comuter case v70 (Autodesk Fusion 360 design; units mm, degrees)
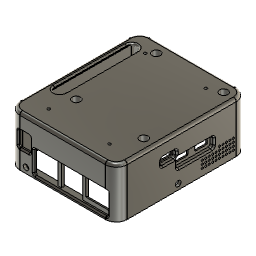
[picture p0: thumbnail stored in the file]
sketch "草图1" plane through (0, 0, 0) normal (0, 0, 1) x axis (1, 0, 0)
  line L1 (64.95, -85) -> (3.05, -85)
  line L2 (68, -3.05) -> (68, -81.95)
  line L3 (68, -3.05) -> (68, -81.95)
  line L4 (0, -81.95) -> (0, -3.05)
  line L5 (3.05, 0) -> (64.95, 0)
  line L6 (0, -81.95) -> (0, -3.05)
  line L7 (3.05, 0) -> (64.95, 0)
  line L8 (64.95, -85) -> (3.05, -85)
  line L9 (3.05, 3) -> (64.95, 3)
  line L10 (71, -3.05) -> (71, -81.95)
  line L11 (64.95, -88) -> (3.05, -88)
  line L12 (-3, -81.95) -> (-3, -3.05)
  line L13 (3.05, 5) -> (64.95, 5)
  line L14 (73, -3.05) -> (73, -81.95)
  line L15 (64.95, -90) -> (3.05, -90)
  line L16 (-5, -81.95) -> (-5, -3.05)
  arc A1 centre (65, -85) radius 0.05 clockwise from (64.95, -85) to (65.05, -84.9996)
  circle C1 centre (15.5, -61.5) radius 4.5
  circle C2 centre (64.5, -61.5) radius 1.475
  circle C3 centre (64.5, -3.5) radius 4.5
  arc A2 centre (68, -3) radius 0.05 clockwise from (68, -3.05) to (67.9996, -2.95)
  arc A3 centre (65, -3) radius 3 clockwise from (65.05, -0.0004) to (67.9996, -2.95)
  arc A4 centre (3, -82) radius 3 clockwise from (2.95, -84.9996) to (0.0004, -82.05)
  arc A5 centre (3, -85) radius 0.05 clockwise from (2.95, -84.9996) to (3.05, -85)
  arc A6 centre (65, -82) radius 3 clockwise from (67.9996, -82.05) to (65.05, -84.9996)
  arc A7 centre (0, -82) radius 0.05 clockwise from (0, -81.95) to (0.0004, -82.05)
  arc A8 centre (65, 0) radius 0.05 clockwise from (65.05, -0.0004) to (64.95, 0)
  arc A9 centre (68, -82) radius 0.05 clockwise from (67.9996, -82.05) to (68, -81.95)
  arc A10 centre (65, -85) radius 0.05 clockwise from (64.95, -85) to (65.05, -84.9996)
  arc A11 centre (3, -82) radius 3 clockwise from (2.95, -84.9996) to (0.0004, -82.05)
  arc A12 centre (3, -3) radius 3 clockwise from (0.0004, -2.95) to (2.95, -0.0004)
  arc A13 centre (68, -82) radius 0.05 clockwise from (67.9996, -82.05) to (68, -81.95)
  arc A14 centre (3, -3) radius 3 clockwise from (0.0004, -2.95) to (2.95, -0.0004)
  arc A15 centre (0, -3) radius 0.05 clockwise from (0.0004, -2.95) to (0, -3.05)
  arc A16 centre (0, -3) radius 0.05 clockwise from (0.0004, -2.95) to (0, -3.05)
  arc A17 centre (3, 0) radius 0.05 clockwise from (3.05, 0) to (2.95, -0.0004)
  arc A18 centre (65, -82) radius 3 clockwise from (67.9996, -82.05) to (65.05, -84.9996)
  arc A19 centre (3, 0) radius 0.05 clockwise from (3.05, 0) to (2.95, -0.0004)
  circle C4 centre (15.5, -3.5) radius 1.475
  arc A20 centre (65, -3) radius 3 clockwise from (65.05, -0.0004) to (67.9996, -2.95)
  circle C5 centre (64.5, -61.5) radius 4.5
  arc A21 centre (3, -85) radius 0.05 clockwise from (2.95, -84.9996) to (3.05, -85)
  circle C6 centre (15.5, -61.5) radius 1.475
  arc A22 centre (0, -82) radius 0.05 clockwise from (0, -81.95) to (0.0004, -82.05)
  circle C7 centre (15.5, -3.5) radius 4.5
  circle C8 centre (64.5, -3.5) radius 1.475
  arc A23 centre (68, -3) radius 0.05 clockwise from (68, -3.05) to (67.9996, -2.95)
  arc A24 centre (65, 0) radius 0.05 clockwise from (65.05, -0.0004) to (64.95, 0)
  arc A25 centre (3.05, 0) radius 3 clockwise from (2.9875, 2.9993) to (3.05, 3)
  arc A26 centre (64.95, 0) radius 3 clockwise from (64.95, 3) to (65.0125, 2.9993)
  arc A27 centre (65.05, -0.0004) radius 3 clockwise from (65.0125, 2.9993) to (65.1, 2.9992)
  arc A28 centre (65, -3) radius 6 clockwise from (65.1, 2.9992) to (70.9992, -2.9)
  arc A29 centre (67.9996, -2.95) radius 3 clockwise from (70.9992, -2.9) to (70.9993, -2.9875)
  arc A30 centre (68, -3.05) radius 3 clockwise from (70.9993, -2.9875) to (71, -3.05)
  arc A31 centre (68, -81.95) radius 3 clockwise from (71, -81.95) to (70.9993, -82.0125)
  arc A32 centre (67.9996, -82.05) radius 3 clockwise from (70.9993, -82.0125) to (70.9992, -82.1)
  arc A33 centre (65, -82) radius 6 clockwise from (70.9992, -82.1) to (65.1, -87.9992)
  arc A34 centre (65.05, -84.9996) radius 3 clockwise from (65.1, -87.9992) to (65.0125, -87.9993)
  arc A35 centre (64.95, -85) radius 3 clockwise from (65.0125, -87.9993) to (64.95, -88)
  arc A36 centre (3.05, -85) radius 3 clockwise from (3.05, -88) to (2.9875, -87.9993)
  arc A37 centre (2.95, -84.9996) radius 3 clockwise from (2.9875, -87.9993) to (2.9, -87.9992)
  arc A38 centre (3, -82) radius 6 clockwise from (2.9, -87.9992) to (-2.9992, -82.1)
  arc A39 centre (0.0004, -82.05) radius 3 clockwise from (-2.9992, -82.1) to (-2.9993, -82.0125)
  arc A40 centre (0, -81.95) radius 3 clockwise from (-2.9993, -82.0125) to (-3, -81.95)
  arc A41 centre (0, -3.05) radius 3 clockwise from (-3, -3.05) to (-2.9993, -2.9875)
  arc A42 centre (0.0004, -2.95) radius 3 clockwise from (-2.9993, -2.9875) to (-2.9992, -2.9)
  arc A43 centre (3, -3) radius 6 clockwise from (-2.9992, -2.9) to (2.9, 2.9992)
  arc A44 centre (2.95, -0.0004) radius 3 clockwise from (2.9, 2.9992) to (2.9875, 2.9993)
  arc A45 centre (3.05, 0) radius 5 clockwise from (2.9792, 4.9995) to (3.05, 5)
  arc A46 centre (64.95, 0) radius 5 clockwise from (64.95, 5) to (65.0208, 4.9995)
  arc A47 centre (65.05, -0.0004) radius 5 clockwise from (65.0208, 4.9995) to (65.1333, 4.9989)
  arc A48 centre (65, -3) radius 8 clockwise from (65.1333, 4.9989) to (72.9989, -2.8667)
  arc A49 centre (67.9996, -2.95) radius 5 clockwise from (72.9989, -2.8667) to (72.9995, -2.9792)
  arc A50 centre (68, -3.05) radius 5 clockwise from (72.9995, -2.9792) to (73, -3.05)
  arc A51 centre (68, -81.95) radius 5 clockwise from (73, -81.95) to (72.9995, -82.0208)
  arc A52 centre (67.9996, -82.05) radius 5 clockwise from (72.9995, -82.0208) to (72.9989, -82.1333)
  arc A53 centre (65, -82) radius 8 clockwise from (72.9989, -82.1333) to (65.1333, -89.9989)
  arc A54 centre (65.05, -84.9996) radius 5 clockwise from (65.1333, -89.9989) to (65.0208, -89.9995)
  arc A55 centre (64.95, -85) radius 5 clockwise from (65.0208, -89.9995) to (64.95, -90)
  arc A56 centre (3.05, -85) radius 5 clockwise from (3.05, -90) to (2.9792, -89.9995)
  arc A57 centre (2.95, -84.9996) radius 5 clockwise from (2.9792, -89.9995) to (2.8667, -89.9989)
  arc A58 centre (3, -82) radius 8 clockwise from (2.8667, -89.9989) to (-4.9989, -82.1333)
  arc A59 centre (0.0004, -82.05) radius 5 clockwise from (-4.9989, -82.1333) to (-4.9995, -82.0208)
  arc A60 centre (0, -81.95) radius 5 clockwise from (-4.9995, -82.0208) to (-5, -81.95)
  arc A61 centre (0, -3.05) radius 5 clockwise from (-5, -3.05) to (-4.9995, -2.9792)
  arc A62 centre (0.0004, -2.95) radius 5 clockwise from (-4.9995, -2.9792) to (-4.9989, -2.8667)
  arc A63 centre (3, -3) radius 8 clockwise from (-4.9989, -2.8667) to (2.8667, 4.9989)
  arc A64 centre (2.95, -0.0004) radius 5 clockwise from (2.8667, 4.9989) to (2.9792, 4.9995)
  circle C9 centre (64.5, -3.5) radius 2.975
  circle C10 centre (15.5, -3.5) radius 2.975
  circle C11 centre (15.5, -61.5) radius 2.975
  circle C12 centre (64.5, -61.5) radius 2.975
  equal C4 C8
  equal C4 C6
  equal C2 C6
  equal C3 C7
  equal C1 C7
  equal C1 C5
  perpendicular L2 L5
  perpendicular L5 L6
  dimension "d1" distance L5 L8 = 85
  dimension "d2" distance L3 L6 = 68
  dimension "d3" diameter C8 = 2.95
  dimension "d4" = 3
  dimension "d5" = 5 (= "3 mm + 2 mm")
  dimension "d6" diameter C3 = 9
  dimension "d7" = 1.5
  dimension "d8" = -1.5
  dimension "d9" = 1.5
  dimension "d10" = -1.5
  dimension "d33" = 2.25
  dimension "d57" = 1.5
extrude "拉伸1" new body sketch "草图1" profile of C1 C3 C5 C7 A25 A26 A27 A29 A30 A31 A32 A34 A35 A36 A37 A39 A40 A41 A42 A44 A38 L12 L9 A28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 against normal blind 2
extrude "拉伸2" add sketch "草图1" profile of A25 A26 A27 A29 A30 A31 A32 A34 A35 A36 A37 A39 A40 A41 A42 A44 A38 L12 L9 A28 A33 A43 L10 L11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 against normal blind 32 (magnitude of "-24 mm - 8 mm")
extrude "拉伸3" add sketch "草图1" profile of C1 C3 C5 C7 C9 C10 C11 C12 against normal blind 10
extrude "拉伸4" sketch "草图1" profile of C2 C4 C6 C8 C9 C10 C11 C12 blind 1.5
extrude "拉伸5" add of existing geometry blind 4.5
sketch "草图2" plane through (0, -90, 0) normal (0, -1, 0) x axis (1, 0, 0)
  line L1 (3.05, 0) -> (64.95, 0)
  line L2 (3.05, -36.5) -> (3.05, 0)
  line L3 (64.95, -36.5) -> (3.05, -36.5)
  line L4 (64.95, 0) -> (64.95, -36.5)
  line L5 (13, -34.5) -> (66.5, -34.5)
  line L6 (13, -18) -> (13, -34.5)
  line L7 (66.5, -18) -> (13, -18)
  line L8 (66.5, -34.5) -> (66.5, -18)
  line L9 (1.5011, -22.6) -> (10.4011, -22.6)
  line L10 (1.5011, -11.5) -> (1.5011, -22.6)
  line L11 (10.4011, -11.5) -> (1.5011, -11.5)
  line L12 (10.4011, -22.6) -> (10.4011, -11.5)
  line L13 (-4.9989, -36.5) -> (-4.9989, 0)
  point P6 (66.5, -34.5)
  point P7 (13, -34.5)
  point P8 (13, -18)
  point P10 (10.4011, -22.6)
  point P11 (1.5011, -22.6)
  point P12 (1.5011, -11.5)
  horizontal L5
  vertical L6
  horizontal L7
  vertical L8
  horizontal L9
  vertical L10
  horizontal L11
  vertical L12
  dimension "d22" distance P6 P7 = 53.5
  dimension "d23" distance P7 P8 = 16.5
  dimension "d24" distance L3 L5 = 2
  dimension "d28" = 16
  dimension "d151" distance P10 P11 = 8.9
  dimension "d152" distance P11 P12 = 11.1
  dimension "d153" distance L10 L13 = 6.5 (= "4.5 mm + 2 mm")
  dimension "d154" distance L1 L11 = 11.5
extrude "拉伸6" cut sketch "草图2" profile of L2 L4 L5 L6 L7 L8 L9 L10 L11 L12 to an object
extrude "拉伸7" cut of existing geometry blind -2
extrude "拉伸21" cut of existing geometry blind -2
sketch "草图3" plane through (0, 0, -36.5) normal (0, 0, -1) x axis (1, 0, 0)
  line L1 (-3, 81.95) -> (-3, 3.05)
  line L2 (64.95, 88) -> (3.05, 88)
  line L3 (71, 3.05) -> (71, 81.95)
  line L4 (3.05, -3) -> (64.95, -3)
  line L5 (64.95, -5) -> (3.05, -5)
  line L6 (73, 81.95) -> (73, 3.05)
  line L7 (3.05, 90) -> (64.95, 90)
  line L8 (-5, 3.05) -> (-5, 81.95)
  line L9 (-2.1962, 85) -> (70.1962, 85)
  arc A1 centre (2.95, 0.0004) radius 3 clockwise from (2.9875, -2.9993) to (2.9, -2.9992)
  arc A2 centre (3, 3) radius 6 clockwise from (2.9, -2.9992) to (-2.9992, 2.9)
  arc A3 centre (0.0004, 2.95) radius 3 clockwise from (-2.9992, 2.9) to (-2.9993, 2.9875)
  arc A4 centre (0, 3.05) radius 3 clockwise from (-2.9993, 2.9875) to (-3, 3.05)
  arc A5 centre (0, 81.95) radius 3 clockwise from (-3, 81.95) to (-2.9993, 82.0125)
  arc A6 centre (0.0004, 82.05) radius 3 clockwise from (-2.9993, 82.0125) to (-2.9992, 82.1)
  arc A7 centre (3, 82) radius 6 clockwise from (-2.9992, 82.1) to (2.9, 87.9992)
  arc A8 centre (2.95, 84.9996) radius 3 clockwise from (2.9, 87.9992) to (2.9875, 87.9993)
  arc A9 centre (3.05, 85) radius 3 clockwise from (2.9875, 87.9993) to (3.05, 88)
  arc A10 centre (64.95, 85) radius 3 clockwise from (64.95, 88) to (65.0125, 87.9993)
  arc A11 centre (65.05, 84.9996) radius 3 clockwise from (65.0125, 87.9993) to (65.1, 87.9992)
  arc A12 centre (65, 82) radius 6 clockwise from (65.1, 87.9992) to (70.9992, 82.1)
  arc A13 centre (67.9996, 82.05) radius 3 clockwise from (70.9992, 82.1) to (70.9993, 82.0125)
  arc A14 centre (68, 81.95) radius 3 clockwise from (70.9993, 82.0125) to (71, 81.95)
  arc A15 centre (68, 3.05) radius 3 clockwise from (71, 3.05) to (70.9993, 2.9875)
  arc A16 centre (67.9996, 2.95) radius 3 clockwise from (70.9993, 2.9875) to (70.9992, 2.9)
  arc A17 centre (65, 3) radius 6 clockwise from (70.9992, 2.9) to (65.1, -2.9992)
  arc A18 centre (65.05, 0.0004) radius 3 clockwise from (65.1, -2.9992) to (65.0125, -2.9993)
  arc A19 centre (64.95, 0) radius 3 clockwise from (65.0125, -2.9993) to (64.95, -3)
  arc A20 centre (3.05, 0) radius 3 clockwise from (3.05, -3) to (2.9875, -2.9993)
  arc A21 centre (2.95, 0.0004) radius 5 clockwise from (2.9792, -4.9995) to (2.8667, -4.9989)
  arc A22 centre (3.05, 0) radius 5 clockwise from (3.05, -5) to (2.9792, -4.9995)
  arc A23 centre (64.95, 0) radius 5 clockwise from (65.0208, -4.9995) to (64.95, -5)
  arc A24 centre (65.05, 0.0004) radius 5 clockwise from (65.1333, -4.9989) to (65.0208, -4.9995)
  arc A25 centre (65, 3) radius 8 clockwise from (72.9989, 2.8667) to (65.1333, -4.9989)
  arc A26 centre (67.9996, 2.95) radius 5 clockwise from (72.9995, 2.9792) to (72.9989, 2.8667)
  arc A27 centre (68, 3.05) radius 5 clockwise from (73, 3.05) to (72.9995, 2.9792)
  arc A28 centre (68, 81.95) radius 5 clockwise from (72.9995, 82.0208) to (73, 81.95)
  arc A29 centre (67.9996, 82.05) radius 5 clockwise from (72.9989, 82.1333) to (72.9995, 82.0208)
  arc A30 centre (65, 82) radius 8 clockwise from (65.1333, 89.9989) to (72.9989, 82.1333)
  arc A31 centre (65.05, 84.9996) radius 5 clockwise from (65.0208, 89.9995) to (65.1333, 89.9989)
  arc A32 centre (64.95, 85) radius 5 clockwise from (64.95, 90) to (65.0208, 89.9995)
  arc A33 centre (3.05, 85) radius 5 clockwise from (2.9792, 89.9995) to (3.05, 90)
  arc A34 centre (2.95, 84.9996) radius 5 clockwise from (2.8667, 89.9989) to (2.9792, 89.9995)
  arc A35 centre (3, 82) radius 8 clockwise from (-4.9989, 82.1333) to (2.8667, 89.9989)
  arc A36 centre (0.0004, 82.05) radius 5 clockwise from (-4.9995, 82.0208) to (-4.9989, 82.1333)
  arc A37 centre (0, 81.95) radius 5 clockwise from (-5, 81.95) to (-4.9995, 82.0208)
  arc A38 centre (0, 3.05) radius 5 clockwise from (-4.9995, 2.9792) to (-5, 3.05)
  arc A39 centre (0.0004, 2.95) radius 5 clockwise from (-4.9989, 2.8667) to (-4.9995, 2.9792)
  arc A40 centre (3, 3) radius 8 clockwise from (2.8667, -4.9989) to (-4.9989, 2.8667)
  point P70 (70.1962, 85)
  point P71 (-2.1962, 85)
  coincident A12 P70
  coincident A7 P71
  parallel L7 L9
  dimension "d105" distance L2 L9 = 3
sketch "草图4" plane through (73, 0, 0) normal (1, 0, 0) x axis (0, 1, 0)
  line L1 (-81.95, 0) -> (-3.05, 0)
  line L2 (-81.95, -36.5) -> (-81.95, 0)
  line L3 (-3.05, -36.5) -> (-81.95, -36.5)
  line L4 (-3.05, 0) -> (-3.05, -36.5)
  line L5 (-42.5, 0) -> (-42.5, -36.5)
  line L6 (-81.95, -17.7) -> (-3.05, -17.7)
  line L7 (-44, -17.7) -> (-21, -17.7)
  line L8 (-44, -21.2) -> (-44, -17.7)
  line L9 (-21, -21.2) -> (-44, -21.2)
  line L10 (-21, -17.7) -> (-21, -21.2)
  line L11 (-32.5, -17.7) -> (-32.5, -21.2)
  line L12 (-30, -17.7) -> (-35, -17.7)
  line L13 (-30, -21.2) -> (-30, -17.7)
  line L14 (-35, -21.2) -> (-30, -21.2)
  line L15 (-35, -17.7) -> (-35, -21.2)
  line L16 (-30, -21.2) -> (-35, -17.7)
  line L17 (-35, -21.2) -> (-30, -17.7)
  line L18 (-81.95, -11.5) -> (-42.5, -11.5)
  line L19 (-56.57, -11.5) -> (-47.07, -11.5)
  line L20 (-56.57, -15) -> (-56.57, -11.5)
  line L21 (-47.07, -15) -> (-56.57, -15)
  line L22 (-47.07, -11.5) -> (-47.07, -15)
  line L23 (-57.57, -10.5) -> (-46.07, -10.5)
  line L24 (-57.57, -16) -> (-57.57, -10.5)
  line L25 (-46.07, -16) -> (-57.57, -16)
  line L26 (-46.07, -10.5) -> (-46.07, -16)
  line L27 (-46, -15.7) -> (-19, -15.7)
  line L28 (-46, -23.2) -> (-46, -15.7)
  line L29 (-19, -23.2) -> (-46, -23.2)
  line L30 (-19, -15.7) -> (-19, -23.2)
  circle C1 centre (-77.5, -30) radius 1.125
  circle C2 centre (-77.5, -30) radius 2.125
  circle C3 centre (-77.5, -30) radius 4.125
  circle C4 centre (-7.5, -30) radius 4.125
  circle C5 centre (-7.5, -30) radius 2.125
  circle C6 centre (-7.5, -30) radius 1.125
  circle C7 centre (-42.5, -26.5) radius 0.75
  circle C8 centre (-42.5, -31.5) radius 0.75
  circle C9 centre (-40, -31.5) radius 0.75
  circle C10 centre (-37.5, -31.5) radius 0.75
  circle C11 centre (-35, -31.5) radius 0.75
  circle C12 centre (-32.5, -31.5) radius 0.75
  circle C13 centre (-42.5, -29) radius 0.75
  circle C14 centre (-40, -29) radius 0.75
  circle C15 centre (-37.5, -29) radius 0.75
  circle C16 centre (-35, -29) radius 0.75
  circle C17 centre (-32.5, -29) radius 0.75
  circle C18 centre (-40, -26.5) radius 0.75
  circle C19 centre (-37.5, -26.5) radius 0.75
  circle C20 centre (-35, -26.5) radius 0.75
  circle C21 centre (-32.5, -26.5) radius 0.75
  circle C22 centre (-42.5, -24) radius 0.75
  circle C23 centre (-40, -24) radius 0.75
  circle C24 centre (-37.5, -24) radius 0.75
  circle C25 centre (-35, -24) radius 0.75
  circle C26 centre (-32.5, -24) radius 0.75
  circle C27 centre (-42.5, -21.5) radius 0.75
  circle C28 centre (-40, -21.5) radius 0.75
  circle C29 centre (-37.5, -21.5) radius 0.75
  circle C30 centre (-35, -21.5) radius 0.75
  circle C31 centre (-32.5, -21.5) radius 0.75
  circle C32 centre (-30, -31.5) radius 0.75
  circle C33 centre (-27.5, -31.5) radius 0.75
  circle C34 centre (-25, -31.5) radius 0.75
  circle C35 centre (-22.5, -31.5) radius 0.75
  circle C36 centre (-20, -31.5) radius 0.75
  circle C37 centre (-17.5, -31.5) radius 0.75
  circle C38 centre (-15, -31.5) radius 0.75
  circle C39 centre (-12.5, -31.5) radius 0.75
  circle C40 centre (-10, -31.5) radius 0.75
  circle C41 centre (-7.5, -31.5) radius 0.75
  circle C42 centre (-5, -31.5) radius 0.75
  circle C43 centre (-30, -29) radius 0.75
  circle C44 centre (-27.5, -29) radius 0.75
  circle C45 centre (-25, -29) radius 0.75
  circle C46 centre (-22.5, -29) radius 0.75
  circle C47 centre (-20, -29) radius 0.75
  circle C48 centre (-17.5, -29) radius 0.75
  circle C49 centre (-15, -29) radius 0.75
  circle C50 centre (-12.5, -29) radius 0.75
  circle C51 centre (-10, -29) radius 0.75
  circle C52 centre (-7.5, -29) radius 0.75
  circle C53 centre (-5, -29) radius 0.75
  circle C54 centre (-30, -26.5) radius 0.75
  circle C55 centre (-27.5, -26.5) radius 0.75
  circle C56 centre (-25, -26.5) radius 0.75
  circle C57 centre (-22.5, -26.5) radius 0.75
  circle C58 centre (-20, -26.5) radius 0.75
  circle C59 centre (-17.5, -26.5) radius 0.75
  circle C60 centre (-15, -26.5) radius 0.75
  circle C61 centre (-12.5, -26.5) radius 0.75
  circle C62 centre (-10, -26.5) radius 0.75
  circle C63 centre (-7.5, -26.5) radius 0.75
  circle C64 centre (-5, -26.5) radius 0.75
  circle C65 centre (-30, -24) radius 0.75
  circle C66 centre (-27.5, -24) radius 0.75
  circle C67 centre (-25, -24) radius 0.75
  circle C68 centre (-22.5, -24) radius 0.75
  circle C69 centre (-20, -24) radius 0.75
  circle C70 centre (-17.5, -24) radius 0.75
  circle C71 centre (-15, -24) radius 0.75
  circle C72 centre (-12.5, -24) radius 0.75
  circle C73 centre (-10, -24) radius 0.75
  circle C74 centre (-7.5, -24) radius 0.75
  circle C75 centre (-5, -24) radius 0.75
  circle C76 centre (-30, -21.5) radius 0.75
  circle C77 centre (-27.5, -21.5) radius 0.75
  circle C78 centre (-25, -21.5) radius 0.75
  circle C79 centre (-22.5, -21.5) radius 0.75
  circle C80 centre (-20, -21.5) radius 0.75
  circle C81 centre (-17.5, -21.5) radius 0.75
  circle C82 centre (-15, -21.5) radius 0.75
  circle C83 centre (-12.5, -21.5) radius 0.75
  circle C84 centre (-10, -21.5) radius 0.75
  circle C85 centre (-7.5, -21.5) radius 0.75
  circle C86 centre (-5, -21.5) radius 0.75
  point P6 (-42.5, -36.5)
  point P7 (-42.5, 0)
  point P14 (-42.5, -26.5)
  point P94 (-3.05, -17.7)
  point P95 (-81.95, -17.7)
  point P96 (-21, -17.7)
  point P100 (-32.5, -21.2)
  point P101 (-32.5, -17.7)
  point P106 (-32.5, -19.45)
  point P102 (-35, -17.7)
  point P107 (-42.5, -11.5)
  point P108 (-81.95, -11.5)
  point P109 (-47.07, -11.5)
  point P8 (-77.5, -30)
  point P97 (-44, -17.7)
  point P98 (-44, -21.2)
  point P110 (-56.57, -11.5)
  point P111 (-56.57, -15)
  point P112 (-47.07, -15)
  midpoint L3 P6
  midpoint L1 P7
  concentric C1 C2
  concentric C2 C3
  symmetric L5 C1 C6
  symmetric L5 C2 C5
  symmetric L5 C3 C4
  coincident L5 P14
  coincident L4 P94
  coincident L2 P95
  perpendicular L2 L6
  horizontal L7
  vertical L8
  horizontal L9
  vertical L10
  coincident L6 P96
  midpoint L9 P100
  midpoint L7 P101
  horizontal L12
  perpendicular L12 L13
  parallel L12 L14
  parallel L13 L15
  coincident L16 P106
  coincident L17 P106
  coincident L7 P102
  midpoint L11 P106
  coincident L5 P107
  coincident L2 P108
  perpendicular L2 L18
  horizontal L19
  vertical L20
  horizontal L21
  vertical L22
  coincident L18 P109
  dimension "d31" distance L5 P8 = 35
  dimension "d32" distance C1 C2 = 1
  dimension "d33" diameter C1 = 2.25
  dimension "d34" distance C2 C3 = 2
  dimension "d57" diameter C7 = 1.5
  dimension "d58" distance L3 P14 = 10
  dimension "d66" distance L1 L6 = 17.7
  dimension "d67" distance P97 P98 = 3.5
  dimension "d69" distance L8 L10 = 23
  dimension "d73" distance L5 L8 = 1.5
  dimension "d74" distance L13 L15 = 5
  dimension "d75" distance L1 L18 = 11.5
  dimension "d76" distance P110 P111 = 3.5
  dimension "d77" distance P111 P112 = 9.5
  dimension "d78" distance L8 L22 = 3.07 (= "4.88 mm - 1.55 mm - ( ( 9.5 - 8.98 ) / 2 ) * 1 mm")
  dimension "d79" = 1
  dimension "d89" = 2 (= "( ( 7.5 - 3.5 ) / 2 ) * 1 mm")
  dimension "d61" R-Pattern1-uDistance = 2.5
  dimension "d62" R-Pattern1-vDistance = 2.5
sketch "草图5" plane through (0, 5, 0) normal (0, 1, 0) x axis (-1, 0, 0)
  line L1 (-64.95, 0) -> (-3.05, 0)
  line L2 (-64.95, -36.5) -> (-64.95, 0)
  line L3 (-3.05, -36.5) -> (-64.95, -36.5)
  line L4 (-3.05, 0) -> (-3.05, -36.5)
  line L5 (-64.95, -36.5) -> (-3.05, -36.5)
  line L6 (-64.95, -16.5) -> (-64.95, -36.5)
  line L7 (-3.05, -16.5) -> (-64.95, -16.5)
  line L8 (-3.05, -36.5) -> (-3.05, -16.5)
  line L9 (-34, -16.5) -> (-34, -36.5)
  line L10 (-10, -11.5) -> (-3.05, -11.5)
  line L11 (-64.95, -11.5) -> (-10, -11.5)
  line L12 (-63.2989, -11.5) -> (-15.2989, -11.5)
  line L13 (-63.2989, -12.5) -> (-63.2989, -11.5)
  line L14 (-15.2989, -12.5) -> (-63.2989, -12.5)
  line L15 (-15.2989, -11.5) -> (-15.2989, -12.5)
  line L16 (-72.9989, -36.5) -> (-72.9989, 0)
  circle C1 centre (-34, -26.5) radius 0.75
  circle C2 centre (-61.5, -31.5) radius 0.75
  circle C3 centre (-59, -31.5) radius 0.75
  circle C4 centre (-56.5, -31.5) radius 0.75
  circle C5 centre (-54, -31.5) radius 0.75
  circle C6 centre (-51.5, -31.5) radius 0.75
  circle C7 centre (-49, -31.5) radius 0.75
  circle C8 centre (-46.5, -31.5) radius 0.75
  circle C9 centre (-44, -31.5) radius 0.75
  circle C10 centre (-41.5, -31.5) radius 0.75
  circle C11 centre (-39, -31.5) radius 0.75
  circle C12 centre (-36.5, -31.5) radius 0.75
  circle C13 centre (-34, -31.5) radius 0.75
  circle C14 centre (-31.5, -31.5) radius 0.75
  circle C15 centre (-29, -31.5) radius 0.75
  circle C16 centre (-26.5, -31.5) radius 0.75
  circle C17 centre (-24, -31.5) radius 0.75
  circle C18 centre (-21.5, -31.5) radius 0.75
  circle C19 centre (-19, -31.5) radius 0.75
  circle C20 centre (-16.5, -31.5) radius 0.75
  circle C21 centre (-14, -31.5) radius 0.75
  circle C22 centre (-11.5, -31.5) radius 0.75
  circle C23 centre (-9, -31.5) radius 0.75
  circle C24 centre (-6.5, -31.5) radius 0.75
  circle C25 centre (-61.5, -29) radius 0.75
  circle C26 centre (-59, -29) radius 0.75
  circle C27 centre (-56.5, -29) radius 0.75
  circle C28 centre (-54, -29) radius 0.75
  circle C29 centre (-51.5, -29) radius 0.75
  circle C30 centre (-49, -29) radius 0.75
  circle C31 centre (-46.5, -29) radius 0.75
  circle C32 centre (-44, -29) radius 0.75
  circle C33 centre (-41.5, -29) radius 0.75
  circle C34 centre (-39, -29) radius 0.75
  circle C35 centre (-36.5, -29) radius 0.75
  circle C36 centre (-34, -29) radius 0.75
  circle C37 centre (-31.5, -29) radius 0.75
  circle C38 centre (-29, -29) radius 0.75
  circle C39 centre (-26.5, -29) radius 0.75
  circle C40 centre (-24, -29) radius 0.75
  circle C41 centre (-21.5, -29) radius 0.75
  circle C42 centre (-19, -29) radius 0.75
  circle C43 centre (-16.5, -29) radius 0.75
  circle C44 centre (-14, -29) radius 0.75
  circle C45 centre (-11.5, -29) radius 0.75
  circle C46 centre (-9, -29) radius 0.75
  circle C47 centre (-6.5, -29) radius 0.75
  circle C48 centre (-61.5, -26.5) radius 0.75
  circle C49 centre (-59, -26.5) radius 0.75
  circle C50 centre (-56.5, -26.5) radius 0.75
  circle C51 centre (-54, -26.5) radius 0.75
  circle C52 centre (-51.5, -26.5) radius 0.75
  circle C53 centre (-49, -26.5) radius 0.75
  circle C54 centre (-46.5, -26.5) radius 0.75
  circle C55 centre (-44, -26.5) radius 0.75
  circle C56 centre (-41.5, -26.5) radius 0.75
  circle C57 centre (-39, -26.5) radius 0.75
  circle C58 centre (-36.5, -26.5) radius 0.75
  circle C59 centre (-31.5, -26.5) radius 0.75
  circle C60 centre (-29, -26.5) radius 0.75
  circle C61 centre (-26.5, -26.5) radius 0.75
  circle C62 centre (-24, -26.5) radius 0.75
  circle C63 centre (-21.5, -26.5) radius 0.75
  circle C64 centre (-19, -26.5) radius 0.75
  circle C65 centre (-16.5, -26.5) radius 0.75
  circle C66 centre (-14, -26.5) radius 0.75
  circle C67 centre (-11.5, -26.5) radius 0.75
  circle C68 centre (-9, -26.5) radius 0.75
  circle C69 centre (-6.5, -26.5) radius 0.75
  circle C70 centre (-61.5, -24) radius 0.75
  circle C71 centre (-59, -24) radius 0.75
  circle C72 centre (-56.5, -24) radius 0.75
  circle C73 centre (-54, -24) radius 0.75
  circle C74 centre (-51.5, -24) radius 0.75
  circle C75 centre (-49, -24) radius 0.75
  circle C76 centre (-46.5, -24) radius 0.75
  circle C77 centre (-44, -24) radius 0.75
  circle C78 centre (-41.5, -24) radius 0.75
  circle C79 centre (-39, -24) radius 0.75
  circle C80 centre (-36.5, -24) radius 0.75
  circle C81 centre (-34, -24) radius 0.75
  circle C82 centre (-31.5, -24) radius 0.75
  circle C83 centre (-29, -24) radius 0.75
  circle C84 centre (-26.5, -24) radius 0.75
  circle C85 centre (-24, -24) radius 0.75
  circle C86 centre (-21.5, -24) radius 0.75
  circle C87 centre (-19, -24) radius 0.75
  circle C88 centre (-16.5, -24) radius 0.75
  circle C89 centre (-14, -24) radius 0.75
  circle C90 centre (-11.5, -24) radius 0.75
  circle C91 centre (-9, -24) radius 0.75
  circle C92 centre (-6.5, -24) radius 0.75
  circle C93 centre (-61.5, -21.5) radius 0.75
  circle C94 centre (-59, -21.5) radius 0.75
  circle C95 centre (-56.5, -21.5) radius 0.75
  circle C96 centre (-54, -21.5) radius 0.75
  circle C97 centre (-51.5, -21.5) radius 0.75
  circle C98 centre (-49, -21.5) radius 0.75
  circle C99 centre (-46.5, -21.5) radius 0.75
  circle C100 centre (-44, -21.5) radius 0.75
  circle C101 centre (-41.5, -21.5) radius 0.75
  circle C102 centre (-39, -21.5) radius 0.75
  circle C103 centre (-36.5, -21.5) radius 0.75
  circle C104 centre (-34, -21.5) radius 0.75
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  point P8 (-64.95, -16.5)
  point P5 (-3.05, -36.5)
  point P6 (-3.05, -36.5)
  point P10 (-34, -36.5)
  point P11 (-34, -16.5)
  point P12 (-34, -26.5)
  point P128 (-3.05, -11.5)
  point P130 (-64.95, -11.5)
  point P131 (-15.2989, -11.5)
  point P127 (-6.4, -15.5)
  point P133 (-63.2989, -12.5)
  point P134 (-15.2989, -12.5)
  point P132 (-63.2989, -11.5)
  point P135 (-54.8989, -18.25)
  horizontal L5
  vertical L6
  horizontal L7
  vertical L8
  coincident L2 P8
  coincident P5 P6
  midpoint L5 P10
  midpoint L7 P11
  midpoint L9 P12
  coincident L4 P128
  perpendicular L4 L10
  coincident L2 P130
  perpendicular L2 L11
  horizontal L12
  vertical L13
  horizontal L14
  vertical L15
  coincident L11 P131
  dimension "d49" distance L5 L7 = 20
  dimension "d50" diameter C1 = 1.5
  dimension "d97" diameter = 6
  dimension "d100" distance L4 P127 = 3.35
  dimension "d101" distance L1 P127 = 15.5
  dimension "d136" distance L1 L11 = 11.5
  dimension "d137" distance P133 P134 = 48 (= "33 mm + 15 mm")
  dimension "d138" distance P132 P133 = 1
  dimension "d143" diameter = 1.5
  dimension "d145" distance P135 L16 = 18.1 (= "14.7 mm + 3.2 mm + 0.2 mm")
  dimension "d148" distance L7 P135 = 1.75
  dimension "d197" distance L13 P135 = 8.4 (= "10 mm - 1.6 mm")
  dimension "d53" R-Pattern1-uDistance = 2.5
  dimension "d54" R-Pattern1-vDistance = 2.5
extrude "拉伸13" cut sketch "草图5" profile of C1 C2 C3 C4 C5 C6 C7 C8 C9 C10 C11 C12 C13 C14 C15 C16 C17 C18 C19 C25 C26 C27 C28 C29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 to an object
extrude "拉伸14" cut sketch "草图4" profile of C33 C34 C35 C36 C37 C38 C39 C40 C41 C42 C44 C45 C46 C47 C48 C49 C50 C51 C52 C53 C55 C56 C57 C58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 to an object
extrude "拉伸15" cut sketch "草图4" profile of L7 L8 L9 L10 L12 L13 L14 L15 L19 L20 L21 L22 L24 L26 L25 L23 L30 L28 L27 L29 to an object
fillet "圆角5" radius 1.5
sketch "草图6" plane through (71, 0, 0) normal (-1, 0, 0) x axis (0, -1, 0)
  line L1 (20.5, -23.2) -> (44.5, -23.2)
  line L2 (19, -17.2) -> (19, -21.7)
  line L3 (44.5, -15.7) -> (20.5, -15.7)
  line L4 (46, -21.7) -> (46, -17.2)
  line L5 (47.57, -16) -> (56.07, -16)
  line L6 (46.07, -12) -> (46.07, -14.5)
  line L7 (56.07, -10.5) -> (47.57, -10.5)
  line L8 (57.57, -14.5) -> (57.57, -12)
  line L9 (3.05, -2) -> (81.95, -2)
  line L10 (3.05, -36.5) -> (3.05, -2)
  line L11 (81.95, -36.5) -> (3.05, -36.5)
  line L12 (81.95, -2) -> (81.95, -36.5)
  line L13 (47, -21.7) -> (47, -17.2)
  line L14 (20.5, -24.2) -> (44.5, -24.2)
  line L15 (18, -17.2) -> (18, -21.7)
  line L16 (44.5, -14.7) -> (20.5, -14.7)
  line L17 (47.57, -17) -> (56.07, -17)
  line L18 (58.57, -14.5) -> (58.57, -12)
  line L19 (56.07, -9.5) -> (47.57, -9.5)
  line L20 (45.07, -12) -> (45.07, -14.5)
  arc A1 centre (20.5, -21.7) radius 1.5 clockwise from (20.5, -23.2) to (19, -21.7)
  arc A2 centre (20.5, -17.2) radius 1.5 clockwise from (19, -17.2) to (20.5, -15.7)
  arc A3 centre (44.5, -17.2) radius 1.5 clockwise from (44.5, -15.7) to (46, -17.2)
  arc A4 centre (44.5, -21.7) radius 1.5 clockwise from (46, -21.7) to (44.5, -23.2)
  arc A5 centre (47.57, -14.5) radius 1.5 clockwise from (47.57, -16) to (46.07, -14.5)
  arc A6 centre (47.57, -12) radius 1.5 clockwise from (46.07, -12) to (47.57, -10.5)
  arc A7 centre (56.07, -12) radius 1.5 clockwise from (56.07, -10.5) to (57.57, -12)
  arc A8 centre (56.07, -14.5) radius 1.5 clockwise from (57.57, -14.5) to (56.07, -16)
  circle C1 centre (20, -26.5) radius 0.75
  circle C2 centre (20, -29) radius 0.75
  circle C3 centre (20, -31.5) radius 0.75
  circle C4 centre (12.5, -26.5) radius 0.75
  circle C5 centre (15, -24) radius 0.75
  circle C6 centre (17.5, -29) radius 0.75
  circle C7 centre (15, -29) radius 0.75
  circle C8 centre (12.5, -29) radius 0.75
  circle C9 centre (15, -31.5) radius 0.75
  circle C10 centre (22.5, -31.5) radius 0.75
  circle C11 centre (25, -31.5) radius 0.75
  circle C12 centre (27.5, -29) radius 0.75
  circle C13 centre (22.5, -29) radius 0.75
  circle C14 centre (25, -29) radius 0.75
  circle C15 centre (5, -24) radius 0.75
  circle C16 centre (10, -24) radius 0.75
  circle C17 centre (25, -26.5) radius 0.75
  circle C18 centre (12.5, -24) radius 0.75
  circle C19 centre (15, -26.5) radius 0.75
  circle C20 centre (17.5, -26.5) radius 0.75
  circle C21 centre (12.5, -31.5) radius 0.75
  circle C22 centre (17.5, -31.5) radius 0.75
  circle C23 centre (27.5, -31.5) radius 0.75
  circle C24 centre (27.5, -26.5) radius 0.75
  circle C25 centre (22.5, -26.5) radius 0.75
  circle C26 centre (7.5, -24) radius 0.75
  arc A9 centre (44.5, -21.7) radius 2.5 clockwise from (47, -21.7) to (44.5, -24.2)
  arc A10 centre (20.5, -21.7) radius 2.5 clockwise from (20.5, -24.2) to (18, -21.7)
  arc A11 centre (20.5, -17.2) radius 2.5 clockwise from (18, -17.2) to (20.5, -14.7)
  arc A12 centre (44.5, -17.2) radius 2.5 clockwise from (44.5, -14.7) to (47, -17.2)
  arc A13 centre (47.57, -14.5) radius 2.5 clockwise from (47.57, -17) to (45.07, -14.5)
  arc A14 centre (56.07, -14.5) radius 2.5 clockwise from (58.57, -14.5) to (56.07, -17)
  arc A15 centre (56.07, -12) radius 2.5 clockwise from (56.07, -9.5) to (58.57, -12)
  arc A16 centre (47.57, -12) radius 2.5 clockwise from (45.07, -12) to (47.57, -9.5)
  circle C27 centre (10, -26.5) radius 0.75
  circle C28 centre (5, -29) radius 0.75
  circle C29 centre (7.5, -31.5) radius 0.75
  circle C30 centre (10, -31.5) radius 0.75
  circle C31 centre (5, -26.5) radius 0.75
  circle C32 centre (7.5, -29) radius 0.75
  circle C33 centre (5, -31.5) radius 0.75
  circle C34 centre (10, -29) radius 0.75
  circle C35 centre (7.5, -26.5) radius 0.75
  dimension "d92" = 1
  dimension "d93" = -1
extrude "拉伸16" add sketch "草图6" profile of L1 A1 L2 A2 L3 A3 L4 A4 L5 A5 L6 A6 L7 A7 L8 A8 L15 L16 A9 L13 L14 A12 A11 A10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 along normal blind 2
extrude "拉伸22" sketch "草图4" profile of L7 L8 L9 L10 L12 L13 L14 L15 L19 L20 L21 L22 L24 L26 L25 L23 L30 L28 L27 L29 blind 1
fillet "圆角17" radius 0.5
fillet "圆角18" radius 0.5
chamfer "倒角2" distance 1
extrude "拉伸17" cut sketch "草图5" to an object
extrude "拉伸20" cut sketch "草图5" to an object
chamfer "倒角3" distance 2
fillet "圆角6" radius 1
extrude "拉伸18" add sketch "草图3" profile of A7 A8 A9 L2 A10 A11 A12 L9 to an object
fillet "圆角7" radius 3
fillet "圆角14" radius 1
fillet "圆角16" radius 1
chamfer "倒角6" distance 1
chamfer "倒角5" distance 1
sketch "草图7" plane through (0, 0, 0) normal (0, 0, 1) x axis (-1, 0, 0)
  line L1 (5, 81.95) -> (5, 3.05)
  line L2 (-64.95, 90) -> (-3.05, 90)
  line L3 (-73, 3.05) -> (-73, 81.95)
  line L4 (-3.05, -5) -> (-64.95, -5)
  line L5 (1, 65) -> (-7, 65)
  line L6 (1, 5) -> (1, 65)
  line L7 (-7, 5) -> (1, 5)
  line L8 (-7, 65) -> (-7, 5)
  line L9 (-33.55, -5) -> (-33.55, 90)
  line L10 (-70, 42.5) -> (-73, 42.5)
  line L11 (5, 42.5) -> (-70, 42.5)
  circle C1 centre (-64.5, 3.5) radius 2.975
  circle C2 centre (-15.5, 61.5) radius 2.975
  circle C3 centre (-15.5, 3.5) radius 2.975
  circle C4 centre (-64.5, 61.5) radius 2.975
  arc A1 centre (-2.95, 0.0004) radius 5 clockwise from (-2.8667, -4.9989) to (-2.9792, -4.9995)
  arc A2 centre (-3, 3) radius 8 clockwise from (4.9989, 2.8667) to (-2.8667, -4.9989)
  arc A3 centre (-0.0004, 2.95) radius 5 clockwise from (4.9995, 2.9792) to (4.9989, 2.8667)
  arc A4 centre (0, 3.05) radius 5 clockwise from (5, 3.05) to (4.9995, 2.9792)
  arc A5 centre (0, 81.95) radius 5 clockwise from (4.9995, 82.0208) to (5, 81.95)
  arc A6 centre (-0.0004, 82.05) radius 5 clockwise from (4.9989, 82.1333) to (4.9995, 82.0208)
  arc A7 centre (-3, 82) radius 8 clockwise from (-2.8667, 89.9989) to (4.9989, 82.1333)
  arc A8 centre (-2.95, 84.9996) radius 5 clockwise from (-2.9792, 89.9995) to (-2.8667, 89.9989)
  arc A9 centre (-3.05, 85) radius 5 clockwise from (-3.05, 90) to (-2.9792, 89.9995)
  arc A10 centre (-64.95, 85) radius 5 clockwise from (-65.0208, 89.9995) to (-64.95, 90)
  arc A11 centre (-65.05, 84.9996) radius 5 clockwise from (-65.1333, 89.9989) to (-65.0208, 89.9995)
  arc A12 centre (-65, 82) radius 8 clockwise from (-72.9989, 82.1333) to (-65.1333, 89.9989)
  arc A13 centre (-67.9996, 82.05) radius 5 clockwise from (-72.9995, 82.0208) to (-72.9989, 82.1333)
  arc A14 centre (-68, 81.95) radius 5 clockwise from (-73, 81.95) to (-72.9995, 82.0208)
  arc A15 centre (-68, 3.05) radius 5 clockwise from (-72.9995, 2.9792) to (-73, 3.05)
  arc A16 centre (-67.9996, 2.95) radius 5 clockwise from (-72.9989, 2.8667) to (-72.9995, 2.9792)
  arc A17 centre (-65, 3) radius 8 clockwise from (-65.1333, -4.9989) to (-72.9989, 2.8667)
  arc A18 centre (-65.05, 0.0004) radius 5 clockwise from (-65.0208, -4.9995) to (-65.1333, -4.9989)
  arc A19 centre (-64.95, 0) radius 5 clockwise from (-64.95, -5) to (-65.0208, -4.9995)
  arc A20 centre (-3.05, 0) radius 5 clockwise from (-2.9792, -4.9995) to (-3.05, -5)
  circle C5 centre (-55.55, 7.5) radius 0.975
  circle C6 centre (-11.55, 7.5) radius 0.975
  circle C7 centre (-11.55, 77.5) radius 0.975
  circle C8 centre (-55.55, 77.5) radius 0.975
  point P55 (-33.55, -5)
  point P54 (-33.55, 90)
  point P51 (1, 65)
  point P52 (1, 5)
  point P59 (-55.55, 7.5)
  horizontal L5
  vertical L6
  horizontal L7
  vertical L8
  perpendicular L3 L10
  perpendicular L9 L11
  coincident L4 P55
  perpendicular L4 L9
  coincident L2 P54
  symmetric L9 C5 C6
  symmetric L11 C5 C8
  symmetric L11 C6 C7
  dimension "d110" distance L6 L8 = 8
  dimension "d111" distance P51 P52 = 60
  dimension "d112" distance L1 L6 = 4
  dimension "d113" distance L4 L7 = 10
  dimension "d124" distance L3 L9 = 39.45 (= "( 78.9 / 2 ) * 1 mm")
  dimension "d125" distance L4 L11 = 47.5 (= "( 95 / 2 ) * 1 mm")
  dimension "d126" distance L11 P59 = 35
  dimension "d127" distance L9 P59 = 22
  dimension "d128" diameter C5 = 1.95
extrude "拉伸19" cut sketch "草图7" profile of L5 L6 L7 L8 C5 C6 C7 C8 against normal blind 2
sketch "草图8" plane through (0, 0, -34.5) normal (0, 0, 1) x axis (-1, 0, 0)
  line L1 (-65.5, 87.9791) -> (-65.5, 88.9821)
  line L2 (-0.0006, 85) -> (-67.9994, 85)
  line L3 (-14, 88) -> (-3.05, 88)
  line L4 (-14, 89) -> (-14, 88)
  line L5 (-27.65, 89) -> (-32.25, 89)
  line L6 (-27.65, 85) -> (-27.65, 89)
  line L7 (-32.25, 85) -> (-27.65, 85)
  line L8 (-32.25, 89) -> (-32.25, 85)
  line L9 (-45.55, 89) -> (-49.85, 89)
  line L10 (-45.55, 85) -> (-45.55, 89)
  line L11 (-49.85, 85) -> (-45.55, 85)
  line L12 (-49.85, 89) -> (-49.85, 85)
  line L13 (-65.75, 85) -> (-65.75, 89)
  line L14 (-49.85, 89) -> (-65.75, 89)
  line L15 (-64.95, 89) -> (-14, 89)
  curve K1 (-65.4375, 88.9863) -> (-65.5, 88.9821)
  line L16 (-27.65, 87.9791) -> (-65.5, 87.9791)
  line L17 (-28.65, 85) -> (-28.65, 89)
  line L18 (-31.25, 89) -> (-31.25, 85)
  line L19 (-48.85, 89) -> (-48.85, 85)
  line L20 (-46.55, 85) -> (-46.55, 89)
  arc A1 centre (-65, 82) radius 6 clockwise from (-70.9992, 82.1) to (-65.5, 87.9791)
  arc A2 centre (-67.9996, 82.05) radius 3 clockwise from (-70.9993, 82.0125) to (-70.9992, 82.1)
  arc A3 centre (-67.9994, 82) radius 3 clockwise from (-70.9993, 82.0125) to (-67.9994, 85)
  arc A4 centre (-0.0006, 82) radius 3 clockwise from (-0.0006, 85) to (2.9993, 82.0125)
  arc A5 centre (-0.0004, 82.05) radius 3 clockwise from (2.9992, 82.1) to (2.9993, 82.0125)
  arc A6 centre (-3, 82) radius 6 clockwise from (-2.9, 87.9992) to (2.9992, 82.1)
  arc A7 centre (-2.95, 84.9996) radius 3 clockwise from (-2.9875, 87.9993) to (-2.9, 87.9992)
  arc A8 centre (-3.05, 85) radius 3 clockwise from (-3.05, 88) to (-2.9875, 87.9993)
  arc A9 centre (-64.95, 85) radius 4 clockwise from (-65.0167, 88.9994) to (-64.95, 89)
  arc A10 centre (-65.05, 84.9996) radius 4 clockwise from (-65.1167, 88.999) to (-65.0167, 88.9994)
  arc A11 centre (-65, 82) radius 7 clockwise from (-65.4375, 88.9863) to (-65.1167, 88.999)
  point P25 (-27.65, 85)
  point P29 (-45.55, 85)
  point P32 (-65.75, 85)
  point P4 (-65.5, 87.9791)
  point P39 (-65.5, 87.9791)
  point P40 (-27.65, 87.9791)
  horizontal L5
  vertical L6
  horizontal L7
  vertical L8
  coincident L2 P25
  horizontal L9
  vertical L10
  horizontal L11
  vertical L12
  coincident L2 P29
  coincident L2 P32
  perpendicular L2 L13
  coincident P4 P39
  coincident L6 P40
  perpendicular L6 L16
  dimension "d167" distance L6 L8 = 4.6
  dimension "d168" = 30.65
  dimension "d169" distance L10 L12 = 4.3
  dimension "d170" distance L8 L10 = 13.3
  dimension "d171" distance L12 L13 = 15.9
  dimension "d177" = 1
  dimension "d178" = 1
  dimension "d179" = 1
  dimension "d180" = 1
fillet "圆角8" radius 4
fillet "圆角9" radius 2
fillet "圆角11" radius 2
fillet "圆角12" radius 1
fillet "圆角13" radius 1
fillet "圆角15" radius 0.5
extrude "拉伸23" add sketch "草图8" profile of A1 A2 A3 L2 L11 L12 L13 L16 L19 along normal blind 3
extrude "拉伸24" add sketch "草图8" profile of L2 L7 L11 L16 L17 L18 L19 L20 along normal blind 20
chamfer "倒角7" distance 1
chamfer "倒角8" distance 2
sketch "草图9" plane through (0, -90, 0) normal (0, -1, 0) x axis (1, 0, 0)
  line L1 (3.05, -2) -> (64.95, -2)
  line L2 (3.05, -10.5) -> (3.05, -2)
  line L3 (9.4011, -10.5) -> (3.05, -10.5)
  line L4 (11.4011, -21.6) -> (11.4011, -12.5)
  line L5 (3.05, -23.6) -> (9.4011, -23.6)
  line L6 (3.05, -36.5) -> (3.05, -23.6)
  line L7 (64.95, -36.5) -> (3.05, -36.5)
  line L8 (64.95, -35.5) -> (64.95, -36.5)
  line L9 (14, -35.5) -> (64.95, -35.5)
  line L10 (12, -19) -> (12, -33.5)
  line L11 (64.95, -17) -> (14, -17)
  line L12 (64.95, -2) -> (64.95, -17)
  line L13 (-4.9989, -36.5) -> (-4.9989, -2)
  arc A1 centre (9.4011, -12.5) radius 2 clockwise from (9.4011, -10.5) to (11.4011, -12.5)
  arc A2 centre (9.4011, -21.6) radius 2 clockwise from (11.4011, -21.6) to (9.4011, -23.6)
  arc A3 centre (14, -33.5) radius 2 clockwise from (14, -35.5) to (12, -33.5)
  arc A4 centre (14, -19) radius 2 clockwise from (12, -19) to (14, -17)
  circle C1 centre (7.5011, -32.5) radius 2
  point P22 (7.5011, -32.5)
  dimension "d183" diameter C1 = 4
  dimension "d184" distance P22 L13 = 12.5
  dimension "d191" distance L7 P22 = 4
sketch "草图10" plane through (73, 0, 0) normal (1, 0, 0) x axis (0, 1, 0)
  line L1 (-81.95, -2) -> (-3.05, -2)
  line L2 (-81.95, -36.5) -> (-81.95, -2)
  line L3 (-3.05, -36.5) -> (-81.95, -36.5)
  line L4 (-3.05, -2) -> (-3.05, -36.5)
  line L5 (-20.5, -14.7) -> (-44.5, -14.7)
  line L6 (-18, -21.7) -> (-18, -17.2)
  line L7 (-44.5, -24.2) -> (-20.5, -24.2)
  line L8 (-47, -17.2) -> (-47, -21.7)
  line L9 (-56.07, -17) -> (-47.57, -17)
  line L10 (-58.57, -12) -> (-58.57, -14.5)
  line L11 (-47.57, -9.5) -> (-56.07, -9.5)
  line L12 (-45.07, -14.5) -> (-45.07, -12)
  line L13 (4.9989, -36.5) -> (4.9989, -2)
  arc A1 centre (-47.57, -14.5) radius 2.5 clockwise from (-45.07, -14.5) to (-45.0845, -14.7693)
  arc A2 centre (-44.5, -17.2) radius 2.5 clockwise from (-45.0845, -14.7693) to (-44.5, -14.7)
  arc A3 centre (-20.5, -17.2) radius 2.5 clockwise from (-20.5, -14.7) to (-18, -17.2)
  arc A4 centre (-20.5, -21.7) radius 2.5 clockwise from (-18, -21.7) to (-20.5, -24.2)
  arc A5 centre (-44.5, -21.7) radius 2.5 clockwise from (-44.5, -24.2) to (-47, -21.7)
  arc A6 centre (-44.5, -17.2) radius 2.5 clockwise from (-47, -17.2) to (-46.9855, -16.9307)
  arc A7 centre (-47.57, -14.5) radius 2.5 clockwise from (-46.9855, -16.9307) to (-47.57, -17)
  arc A8 centre (-56.07, -14.5) radius 2.5 clockwise from (-56.07, -17) to (-58.57, -14.5)
  arc A9 centre (-56.07, -12) radius 2.5 clockwise from (-58.57, -12) to (-56.07, -9.5)
  arc A10 centre (-47.57, -12) radius 2.5 clockwise from (-47.57, -9.5) to (-45.07, -12)
  circle C1 centre (-7.5, -26.5) radius 0.75
  circle C2 centre (-10, -29) radius 0.75
  circle C3 centre (-10, -26.5) radius 0.75
  circle C4 centre (-20, -26.5) radius 0.75
  circle C5 centre (-20, -29) radius 0.75
  circle C6 centre (-27.5, -29) radius 0.75
  circle C7 centre (-15, -26.5) radius 0.75
  circle C8 centre (-17.5, -26.5) radius 0.75
  circle C9 centre (-15, -29) radius 0.75
  circle C10 centre (-12.5, -29) radius 0.75
  circle C11 centre (-17.5, -29) radius 0.75
  circle C12 centre (-15, -24) radius 0.75
  circle C13 centre (-12.5, -24) radius 0.75
  circle C14 centre (-22.5, -29) radius 0.75
  circle C15 centre (-25, -29) radius 0.75
  circle C16 centre (-5, -24) radius 0.75
  circle C17 centre (-10, -31.5) radius 0.75
  circle C18 centre (-5, -26.5) radius 0.75
  circle C19 centre (-7.5, -29) radius 0.75
  circle C20 centre (-5, -31.5) radius 0.75
  circle C21 centre (-10, -24) radius 0.75
  circle C22 centre (-25, -26.5) radius 0.75
  circle C23 centre (-20, -31.5) radius 0.75
  circle C24 centre (-25, -31.5) radius 0.75
  circle C25 centre (-27.5, -31.5) radius 0.75
  circle C26 centre (-12.5, -31.5) radius 0.75
  circle C27 centre (-17.5, -31.5) radius 0.75
  circle C28 centre (-15, -31.5) radius 0.75
  circle C29 centre (-22.5, -31.5) radius 0.75
  circle C30 centre (-12.5, -26.5) radius 0.75
  circle C31 centre (-27.5, -26.5) radius 0.75
  circle C32 centre (-22.5, -26.5) radius 0.75
  circle C33 centre (-7.5, -24) radius 0.75
  circle C34 centre (-7.5, -31.5) radius 0.75
  circle C35 centre (-5, -29) radius 0.75
  circle C36 centre (-45.0011, -32.5) radius 2
  point P67 (-45.0011, -32.5)
  dimension "d185" diameter C36 = 4
  dimension "d186" distance P67 L13 = 50
  dimension "d192" distance L3 P67 = 4
extrude "拉伸25" cut sketch "草图9" profile of C1 to an object
extrude "拉伸26" cut sketch "草图10" profile of C36 to an object
sketch "草图11" plane through (0, 0, -36.5) normal (0, 0, -1) x axis (1, 0, 0)
  line L1 (-3, 81.95) -> (-3, 3.05)
  line L2 (67.9994, 85) -> (0.0006, 85)
  line L3 (71, 3.05) -> (71, 81.95)
  line L4 (3.05, -3) -> (64.95, -3)
  line L5 (64.95, -5) -> (3.05, -5)
  line L6 (73, 81.95) -> (73, 3.05)
  line L7 (3.05, 90) -> (64.95, 90)
  line L8 (-5, 3.05) -> (-5, 81.95)
  arc A1 centre (2.95, 0.0004) radius 3 clockwise from (2.9875, -2.9993) to (2.9, -2.9992)
  arc A2 centre (3, 3) radius 6 clockwise from (2.9, -2.9992) to (-2.9992, 2.9)
  arc A3 centre (0.0004, 2.95) radius 3 clockwise from (-2.9992, 2.9) to (-2.9993, 2.9875)
  arc A4 centre (0, 3.05) radius 3 clockwise from (-2.9993, 2.9875) to (-3, 3.05)
  arc A5 centre (0, 81.95) radius 3 clockwise from (-3, 81.95) to (-2.9993, 82.0125)
  arc A6 centre (0.0006, 82) radius 3 clockwise from (-2.9993, 82.0125) to (0.0006, 85)
  arc A7 centre (67.9994, 82) radius 3 clockwise from (67.9994, 85) to (70.9993, 82.0125)
  arc A8 centre (68, 81.95) radius 3 clockwise from (70.9993, 82.0125) to (71, 81.95)
  arc A9 centre (68, 3.05) radius 3 clockwise from (71, 3.05) to (70.9993, 2.9875)
  arc A10 centre (67.9996, 2.95) radius 3 clockwise from (70.9993, 2.9875) to (70.9992, 2.9)
  arc A11 centre (65, 3) radius 6 clockwise from (70.9992, 2.9) to (65.1, -2.9992)
  arc A12 centre (65.05, 0.0004) radius 3 clockwise from (65.1, -2.9992) to (65.0125, -2.9993)
  arc A13 centre (64.95, 0) radius 3 clockwise from (65.0125, -2.9993) to (64.95, -3)
  arc A14 centre (3.05, 0) radius 3 clockwise from (3.05, -3) to (2.9875, -2.9993)
  arc A15 centre (2.95, 0.0004) radius 5 clockwise from (2.9792, -4.9995) to (2.8667, -4.9989)
  arc A16 centre (3.05, 0) radius 5 clockwise from (3.05, -5) to (2.9792, -4.9995)
  arc A17 centre (64.95, 0) radius 5 clockwise from (65.0208, -4.9995) to (64.95, -5)
  arc A18 centre (65.05, 0.0004) radius 5 clockwise from (65.1333, -4.9989) to (65.0208, -4.9995)
  arc A19 centre (65, 3) radius 8 clockwise from (72.9989, 2.8667) to (65.1333, -4.9989)
  arc A20 centre (67.9996, 2.95) radius 5 clockwise from (72.9995, 2.9792) to (72.9989, 2.8667)
  arc A21 centre (68, 3.05) radius 5 clockwise from (73, 3.05) to (72.9995, 2.9792)
  arc A22 centre (68, 81.95) radius 5 clockwise from (72.9995, 82.0208) to (73, 81.95)
  arc A23 centre (67.9996, 82.05) radius 5 clockwise from (72.9989, 82.1333) to (72.9995, 82.0208)
  arc A24 centre (65, 82) radius 8 clockwise from (65.1333, 89.9989) to (72.9989, 82.1333)
  arc A25 centre (65.05, 84.9996) radius 5 clockwise from (65.0208, 89.9995) to (65.1333, 89.9989)
  arc A26 centre (64.95, 85) radius 5 clockwise from (64.95, 90) to (65.0208, 89.9995)
  arc A27 centre (3.05, 85) radius 5 clockwise from (2.9792, 89.9995) to (3.05, 90)
  arc A28 centre (2.95, 84.9996) radius 5 clockwise from (2.8667, 89.9989) to (2.9792, 89.9995)
  arc A29 centre (3, 82) radius 8 clockwise from (-4.9989, 82.1333) to (2.8667, 89.9989)
  arc A30 centre (0.0004, 82.05) radius 5 clockwise from (-4.9995, 82.0208) to (-4.9989, 82.1333)
  arc A31 centre (0, 81.95) radius 5 clockwise from (-5, 81.95) to (-4.9995, 82.0208)
  arc A32 centre (0, 3.05) radius 5 clockwise from (-4.9995, 2.9792) to (-5, 3.05)
  arc A33 centre (0.0004, 2.95) radius 5 clockwise from (-4.9989, 2.8667) to (-4.9995, 2.9792)
  arc A34 centre (3, 3) radius 8 clockwise from (2.8667, -4.9989) to (-4.9989, 2.8667)
fillet "圆角19" radius 0.5
fillet "圆角20" radius 0.5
